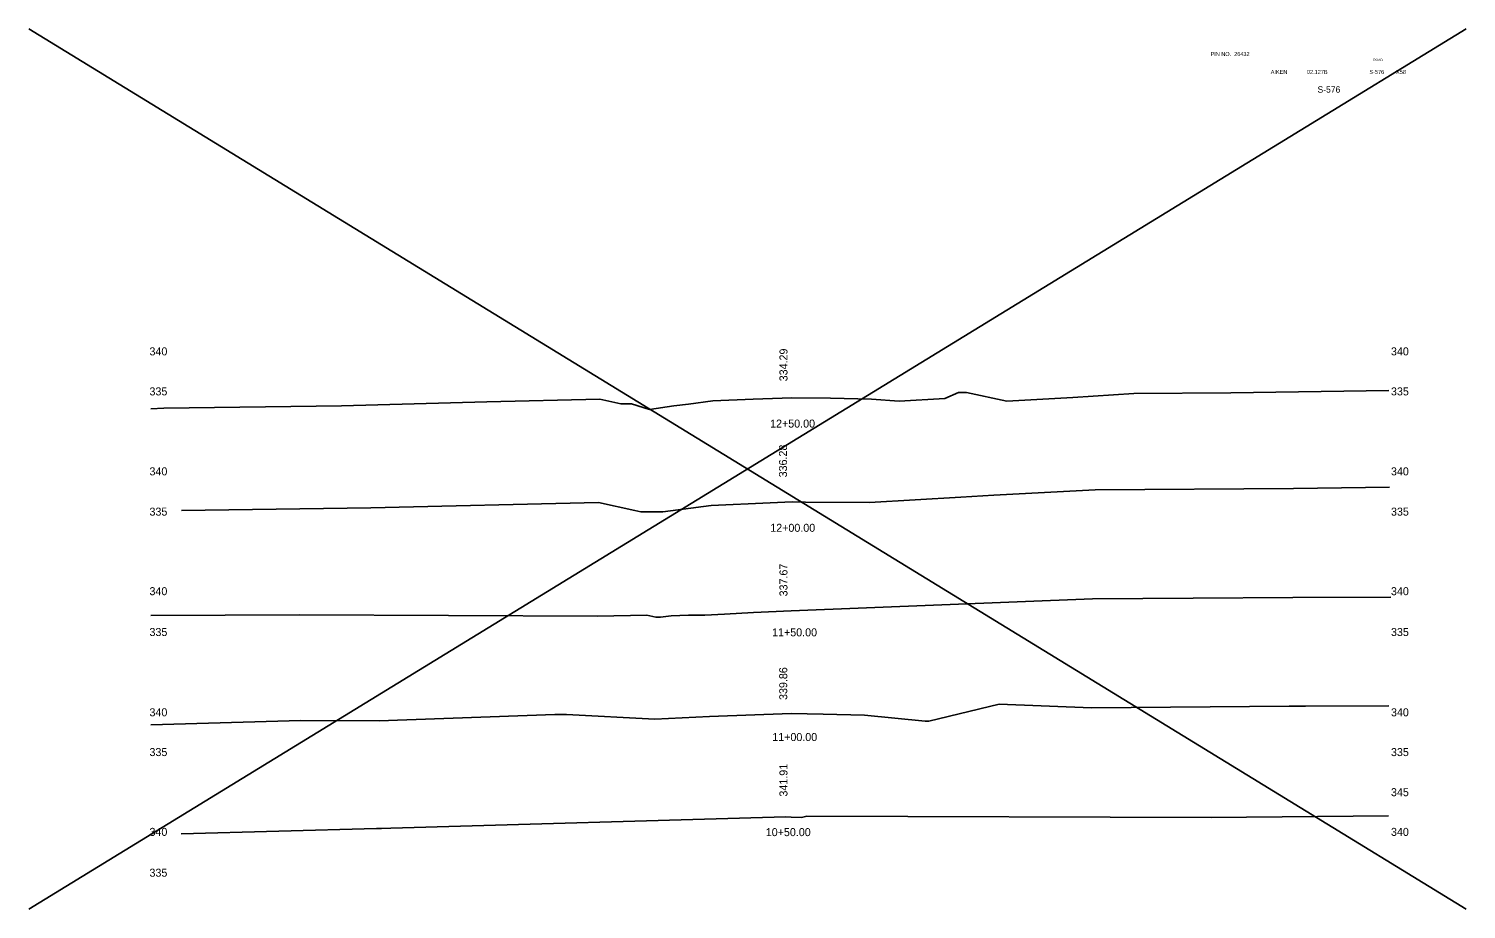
# Model space of a CAD drawing. Extents: x 985 to 1164, y 1005 to 1115.
import ezdxf

# ---------------------------------------------------------------- set-up
doc = ezdxf.new("R2010")
doc.units = 0
for name, color, linetype in [('Level 1', 7, 'Continuous'), ('Level 10', 7, 'Continuous'), ('Level 3', 7, 'Continuous'), ('Level 41', 7, 'Continuous'), ('Level 60', 7, 'Continuous')]:
    doc.layers.add(name, color=color, linetype=linetype)

msp = doc.modelspace()

# ---------------------------------------------------------------- linework, layer by layer
at = {"layer": 'Level 10'}
for p, q in [((984.74, 1005.41), (1164.34, 1115.41)), ((1164.34, 1005.41), (984.74, 1115.41))]:
    msp.add_line(p, q, dxfattribs=at)
at = {"layer": 'Level 60'}
for p, q in [((1023.8, 1068.31), (1041.96, 1068.81)), ((1041.96, 1068.81), (1056.07, 1069.14)), ((1056.07, 1069.14), (1058.7, 1068.56)), ((1067.17, 1068.52), (1070.2, 1068.91)), ((1070.2, 1068.91), (1075.25, 1069.13)), ((1075.25, 1069.13), (1080.07, 1069.29)), ((1080.07, 1069.29), (1084.92, 1069.25)), ((1084.92, 1069.25), (1090.02, 1069.12)), ((1090.02, 1069.12), (1093.47, 1068.87)), ((1093.47, 1068.87), (1099.2, 1069.22)), ((1099.2, 1069.22), (1100.9, 1069.97)), ((1100.9, 1069.97), (1101.89, 1069.97)), ((1101.89, 1069.97), (1106.92, 1068.89)), ((1106.92, 1068.89), (1115.17, 1069.33)), ((1115.17, 1069.33), (1122.8, 1069.85)), ((1122.8, 1069.85), (1134.91, 1069.93)), ((1134.91, 1069.93), (1154.68, 1070.22)), ((1000, 1067.91), (1001.6, 1067.99)), ((1001.6, 1067.99), (1023.8, 1068.31)), ((1058.7, 1068.56), (1060.06, 1068.56)), ((1060.06, 1068.56), (1062.28, 1067.82)), ((1062.28, 1067.82), (1065.34, 1068.3)), ((1065.34, 1068.3), (1067.17, 1068.52)), ((1117.96, 1057.79), (1142.77, 1057.95)), ((1142.77, 1057.95), (1154.74, 1058.13)), ((1027.49, 1055.57), (1055.92, 1056.23)), ((1055.92, 1056.23), (1060.46, 1055.23)), ((1070, 1055.85), (1077.37, 1056.17)), ((1077.37, 1056.17), (1080.13, 1056.29)), ((1080.13, 1056.29), (1081.79, 1056.27)), ((1081.79, 1056.27), (1089.77, 1056.2)), ((1089.77, 1056.2), (1101.19, 1056.9)), ((1101.19, 1056.9), (1105.3, 1057.12)), ((1105.3, 1057.12), (1117.96, 1057.79)), ((1003.83, 1055.22), (1027.49, 1055.57)), ((1060.46, 1055.23), (1061.22, 1055.06)), ((1061.22, 1055.06), (1063.95, 1055.07)), ((1063.95, 1055.07), (1070, 1055.85)), ((1080, 1042.67), (1117.66, 1044.18)), ((1117.66, 1044.18), (1130.23, 1044.28)), ((1130.23, 1044.28), (1142.66, 1044.37)), ((1142.66, 1044.37), (1154.93, 1044.41)), ((1000, 1042.11), (1018.56, 1042.19)), ((1018.56, 1042.19), (1055.81, 1042)), ((1055.81, 1042), (1061.96, 1042.14)), ((1061.96, 1042.14), (1063.1, 1041.89)), ((1063.1, 1041.89), (1063.68, 1041.89)), ((1063.68, 1041.89), (1064.98, 1042.06)), ((1064.98, 1042.06), (1067.15, 1042.15)), ((1067.15, 1042.15), (1069.21, 1042.14)), ((1069.21, 1042.14), (1071.65, 1042.29)), ((1071.65, 1042.29), (1075.29, 1042.48)), ((1075.29, 1042.48), (1080, 1042.67)), ((1097.18, 1028.89), (1105.99, 1031.04)), ((1105.99, 1031.04), (1117.52, 1030.55)), ((1028.52, 1028.93), (1050.48, 1029.74)), ((1050.48, 1029.74), (1051.24, 1029.74)), ((1051.24, 1029.74), (1051.94, 1029.73)), ((1051.94, 1029.73), (1062.96, 1029.17)), ((1062.96, 1029.17), (1069.8, 1029.48)), ((1069.8, 1029.48), (1080, 1029.86)), ((1080, 1029.86), (1083.99, 1029.78)), ((1083.99, 1029.78), (1089.16, 1029.67)), ((1089.16, 1029.67), (1096.74, 1028.9)), ((1117.52, 1030.55), (1142.23, 1030.76)), ((1142.23, 1030.76), (1143.13, 1030.76)), ((1143.13, 1030.76), (1144.27, 1030.77)), ((1144.27, 1030.77), (1154.65, 1030.8)), ((1000, 1028.44), (1018.74, 1028.97)), ((1018.74, 1028.97), (1028.52, 1028.93)), ((1096.74, 1028.9), (1097.18, 1028.89)), ((1029.96, 1015.52), (1079.33, 1016.93)), ((1079.33, 1016.93), (1080, 1016.91)), ((1080, 1016.91), (1081.29, 1016.88)), ((1081.29, 1016.88), (1081.94, 1017.04)), ((1081.94, 1017.04), (1132.45, 1016.88)), ((1132.45, 1016.88), (1154.62, 1017.08)), ((1003.77, 1014.83), (1028.18, 1015.49)), ((1028.18, 1015.49), (1028.8, 1015.51)), ((1028.8, 1015.51), (1029.96, 1015.52))]:
    msp.add_line(p, q, dxfattribs=at)

# ---------------------------------------------------------------- texts
at = {"layer": 'Level 1'}
for s, p in [('12+50.00', (1077.36, 1065.58)), ('12+00.00', (1077.38, 1052.56)), ('11+50.00', (1077.61, 1039.5)), ('11+00.00', (1077.63, 1026.42)), ('10+50.00', (1076.82, 1014.54))]:
    msp.add_text(s, height=1, dxfattribs=at).set_placement(p)
at = {"layer": 'Level 10'}
msp.add_text('PIN NO.  26432', height=0.5, dxfattribs=at).set_placement((1132.39, 1112))
for s, p in [('334.29', (1079.53, 1071.36)), ('336.28', (1079.47, 1059.36)), ('337.67', (1079.53, 1044.49)), ('339.86', (1079.5, 1031.55)), ('341.91', (1079.53, 1019.48))]:
    msp.add_text(s, height=1, rotation=90, dxfattribs=at).set_placement(p)
at = {"layer": 'Level 3'}
for s, height, p in [('ROAD', 0.3, (1152.71, 1111.36)), (' 340', 1, (999.45, 1074.6)), (' 340', 1, (1154.56, 1074.6)), (' 335', 1, (999.45, 1069.6)), (' 335', 1, (1154.56, 1069.6)), (' 340', 1, (999.45, 1059.61)), (' 340', 1, (1154.56, 1059.61)), (' 335', 1, (999.45, 1054.58)), (' 335', 1, (1154.56, 1054.58)), (' 340', 1, (999.45, 1044.64)), (' 340', 1, (1154.56, 1044.64)), (' 335', 1, (999.45, 1039.54)), (' 335', 1, (1154.56, 1039.54)), (' 340', 1, (999.45, 1029.51)), (' 340', 1, (1154.56, 1029.51)), (' 335', 1, (999.45, 1024.54)), (' 335', 1, (1154.56, 1024.54)), (' 345', 1, (1154.56, 1019.53)), (' 340', 1, (999.45, 1014.57)), (' 340', 1, (1154.56, 1014.57)), (' 335', 1, (999.45, 1009.47))]:
    msp.add_text(s, height=height, dxfattribs=at).set_placement(p)
at = {"layer": 'Level 41'}
for s, height, p in [('AIKEN', 0.5, (1139.91, 1109.76)), ('02.127B', 0.5, (1144.44, 1109.76)), ('S-576', 0.5, (1152.24, 1109.76)), ('X58', 0.5, (1155.57, 1109.76)), ('S-576', 0.8, (1145.75, 1107.42))]:
    msp.add_text(s, height=height, dxfattribs=at).set_placement(p)

doc.saveas('drawing.dxf')
